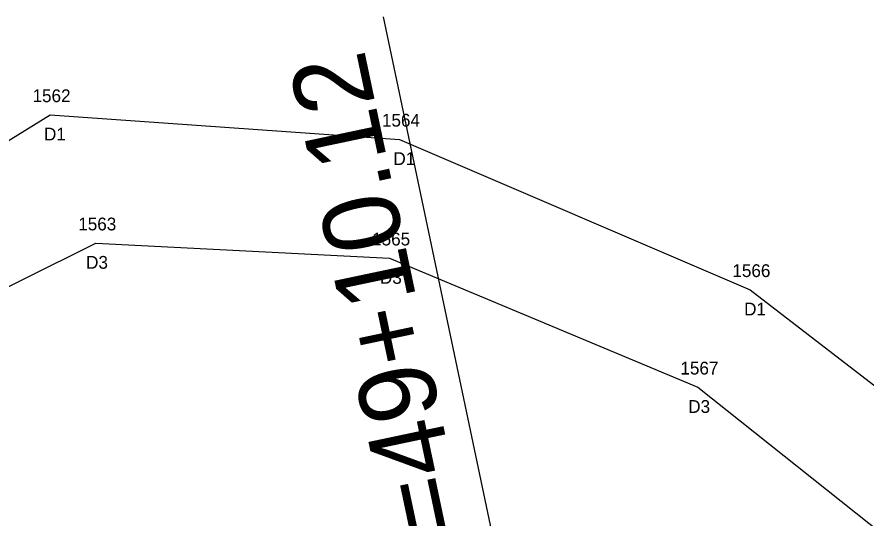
# Model space of a CAD drawing. Extents: x 1965304 to 1970247, y 1117014 to 1118201.
# Drawn here: x 1966632.2 to 1966698.6, y 1117496.8 to 1117536 of the extents above; entities that cross this region are included whole.
import ezdxf

# ---------------------------------------------------------------- set-up
doc = ezdxf.new("R2010")
doc.units = 0
for name, color, linetype in [('RD_EX_Driveway', 7, 'Continuous'), ('RD_EX_Driveway_txCode', 7, 'Continuous'), ('RD_HC_Data', 7, 'Continuous'), ('RD_SMD_Locator', 7, 'Continuous')]:
    doc.layers.add(name, color=color, linetype=linetype)

msp = doc.modelspace()

# ---------------------------------------------------------------- linework, layer by layer
at = {"layer": 'RD_EX_Driveway'}
for points in [[(1966578.028, 1117435.239), (1966571.581, 1117480.753), (1966567.97, 1117515.311), (1966576.556, 1117516.6), (1966582.112, 1117483.547), (1966603.624, 1117509.102), (1966634.749, 1117528.345), (1966662.085, 1117526.43), (1966689.524, 1117514.663), (1966711.523, 1117497.722), (1966730.008, 1117478.512), (1966744.031, 1117462.693), (1966734.107, 1117458.19)], [(1966589.3, 1117436.331), (1966587.977, 1117456.65), (1966594.083, 1117483.042), (1966609.697, 1117504.074), (1966638.325, 1117518.314), (1966661.317, 1117517.134), (1966685.434, 1117507.038), (1966705.558, 1117491.043), (1966722.871, 1117472.119), (1966734.107, 1117458.19)]]:
    msp.add_lwpolyline(points, dxfattribs=at)
at = {"layer": 'RD_HC_Data'}
msp.add_line((1966684.871, 1117421.945), (1966660.825, 1117536.006), dxfattribs=at)
at = {"layer": 'RD_SMD_Locator'}
for centre in [(1966634.749, 1117528.345), (1966634.749, 1117528.345), (1966662.085, 1117526.43), (1966662.085, 1117526.43), (1966638.325, 1117518.314), (1966638.325, 1117518.314), (1966661.317, 1117517.134), (1966661.317, 1117517.134), (1966689.524, 1117514.663), (1966689.524, 1117514.663), (1966685.434, 1117507.038), (1966685.434, 1117507.038)]:
    msp.add_circle(centre, 0.001, dxfattribs=at)

# ---------------------------------------------------------------- texts
at = {"layer": 'RD_EX_Driveway_txCode'}
for s, p in [('1562', (1966633.379, 1117529.345)), ('1562', (1966633.379, 1117529.345)), ('1564', (1966660.715, 1117527.43)), ('1564', (1966660.715, 1117527.43)), ('D1', (1966634.276, 1117526.345)), ('D1', (1966634.276, 1117526.345)), ('D1', (1966661.612, 1117524.43)), ('D1', (1966661.612, 1117524.43)), ('1563', (1966636.955, 1117519.314)), ('1563', (1966636.955, 1117519.314)), ('1565', (1966659.947, 1117518.134)), ('1565', (1966659.947, 1117518.134)), ('D3', (1966637.569, 1117516.314)), ('D3', (1966637.569, 1117516.314)), ('1566', (1966688.13, 1117515.663)), ('1566', (1966688.13, 1117515.663)), ('D3', (1966660.561, 1117515.134)), ('D3', (1966660.561, 1117515.134)), ('D1', (1966689.051, 1117512.663)), ('D1', (1966689.051, 1117512.663)), ('1567', (1966684.064, 1117508.038)), ('1567', (1966684.064, 1117508.038)), ('D3', (1966684.678, 1117505.038)), ('D3', (1966684.678, 1117505.038))]:
    msp.add_text(s, height=1, dxfattribs=at).set_placement(p)
at = {"layer": 'RD_HC_Data'}
msp.add_text('PC=49+10.12', height=6, rotation=101.90472, dxfattribs=at).set_placement((1966669.506, 1117485.135))

doc.saveas('drawing.dxf')
